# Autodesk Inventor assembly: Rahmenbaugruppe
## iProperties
Created: 2003-03
Part Number: Rahmenbaugruppe
Document SubType Name: Baugruppe
Designer: Administrator
Control State: 0
Master: False
Checked Out: False
Shininess: 20.0
Angle Display Precision: 2
Document Length Units: 11269
Document Angle Units: 11279
Document Time Units: 11290
Document Mass Units: 11283
Document Length Units Precision: 3
Document Angle Units Precision: 2
Density: 0.0
Volumn: 0.0
Area: 0.0
PropertySet Name: Model Information
Author: Administrator
